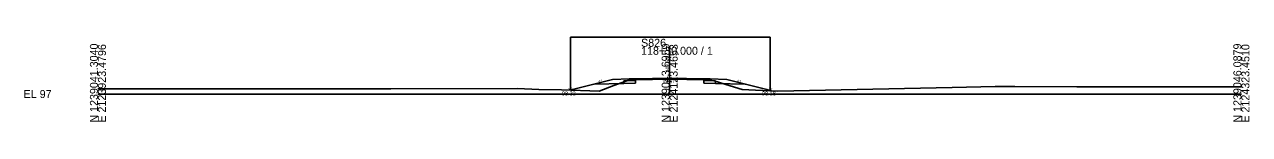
# Model space of a CAD drawing. Extents: x 2119282 to 2119710, y 1215030 to 1220057.
# Drawn here: x 2119281.9 to 2119710.4, y 1217030.1 to 1217059.7 of the extents above; entities that cross this region are included whole.
import ezdxf

# ---------------------------------------------------------------- set-up
doc = ezdxf.new("R2010")
doc.units = 0
for name, color, linetype in [('XS_CELL', 7, 'Continuous'), ('XS_M_DITCH', 7, 'Continuous'), ('XS_P_FINISHED_GRADE', 7, 'Continuous'), ('XS_P_FINISHED_GRADE_ELEV_TX', 7, 'Continuous'), ('XS_P_SUBGRADE_GRANULAR', 7, 'Continuous'), ('XS_P_SUBGRADE_PAVEMENT', 7, 'Continuous'), ('XS_P_TX_DCH', 7, 'Continuous'), ('XS_P_TX_FS_BS', 7, 'Continuous'), ('XS_X_GROUND', 7, 'Continuous'), ('XS_X_GROUND_TX', 7, 'Continuous')]:
    doc.layers.add(name, color=color, linetype=linetype)

msp = doc.modelspace()

# ---------------------------------------------------------------- linework, layer by layer
at = {"layer": 'XS_CELL'}
for p, q in [((2119507.6, 1217039.8), (2119507.6, 1217056.36)), ((2119307.6, 1217039.8), (2119507.6, 1217039.8)), ((2119507.6, 1217039.8), (2119707.6, 1217039.8))]:
    msp.add_line(p, q, dxfattribs=at)
at = {"layer": 'XS_M_DITCH'}
for p, q in [((2119472.87, 1217041.13), (2119472.87, 1217059.68)), ((2119472.87, 1217059.68), (2119542.77, 1217059.68)), ((2119542.77, 1217040.98), (2119542.77, 1217059.68))]:
    msp.add_line(p, q, dxfattribs=at)
at = {"layer": 'XS_P_FINISHED_GRADE'}
for p, q in [((2119473.6, 1217041.37), (2119472.87, 1217041.13)), ((2119487.6, 1217044.87), (2119473.6, 1217041.37)), ((2119493.6, 1217045.11), (2119487.6, 1217044.87)), ((2119495.6, 1217045.15), (2119493.6, 1217045.11)), ((2119507.6, 1217045.39), (2119495.6, 1217045.15)), ((2119507.6, 1217045.39), (2119519.6, 1217045.15)), ((2119519.6, 1217045.15), (2119521.6, 1217045.11)), ((2119521.6, 1217045.11), (2119527.6, 1217044.87)), ((2119527.6, 1217044.87), (2119541.6, 1217041.37)), ((2119541.6, 1217041.37), (2119542.77, 1217040.98))]:
    msp.add_line(p, q, dxfattribs=at)
at = {"layer": 'XS_P_SUBGRADE_GRANULAR'}
for p, q in [((2119491.6, 1217043.49), (2119481.24, 1217043.28)), ((2119492.95, 1217044.52), (2119491.6, 1217044.46)), ((2119491.6, 1217043.49), (2119491.6, 1217044.46)), ((2119495.6, 1217043.57), (2119491.6, 1217043.49)), ((2119495.6, 1217043.57), (2119495.61, 1217044.57)), ((2119519.6, 1217043.57), (2119519.59, 1217044.57)), ((2119519.6, 1217043.57), (2119523.6, 1217043.49)), ((2119522.26, 1217044.52), (2119523.6, 1217044.46)), ((2119523.6, 1217043.49), (2119523.6, 1217044.46)), ((2119523.6, 1217043.49), (2119533.97, 1217043.28))]:
    msp.add_line(p, q, dxfattribs=at)
at = {"layer": 'XS_P_SUBGRADE_PAVEMENT'}
for p, q in [((2119493.1, 1217044.77), (2119492.95, 1217044.52)), ((2119495.61, 1217044.57), (2119492.95, 1217044.52)), ((2119493.6, 1217045.11), (2119493.1, 1217044.77)), ((2119507.6, 1217045.06), (2119495.61, 1217044.82)), ((2119495.61, 1217044.57), (2119495.61, 1217044.82)), ((2119507.6, 1217045.06), (2119519.6, 1217044.82)), ((2119519.59, 1217044.57), (2119519.6, 1217044.82)), ((2119519.59, 1217044.57), (2119522.26, 1217044.52)), ((2119521.6, 1217045.11), (2119522.11, 1217044.77)), ((2119522.11, 1217044.77), (2119522.26, 1217044.52))]:
    msp.add_line(p, q, dxfattribs=at)
at = {"layer": 'XS_X_GROUND'}
for p, q in [((2119307.6, 1217041.57), (2119317.98, 1217041.6)), ((2119317.98, 1217041.6), (2119364.19, 1217041.64)), ((2119364.19, 1217041.64), (2119410.07, 1217041.64)), ((2119410.07, 1217041.64), (2119454.34, 1217041.72)), ((2119454.34, 1217041.72), (2119461.78, 1217041.44)), ((2119461.78, 1217041.44), (2119469.79, 1217041.24)), ((2119469.79, 1217041.24), (2119482.91, 1217040.76)), ((2119482.91, 1217040.76), (2119488.07, 1217042.78)), ((2119488.07, 1217042.78), (2119493.96, 1217044.9)), ((2119493.96, 1217044.9), (2119496.66, 1217045.12)), ((2119496.66, 1217045.12), (2119498.93, 1217045.16)), ((2119498.93, 1217045.16), (2119507.6, 1217045.31)), ((2119507.6, 1217045.31), (2119508.36, 1217045.32)), ((2119508.36, 1217045.32), (2119520.27, 1217044.72)), ((2119520.27, 1217044.72), (2119523.16, 1217044.44)), ((2119523.16, 1217044.44), (2119528.81, 1217042.63)), ((2119528.81, 1217042.63), (2119532.91, 1217041.39)), ((2119532.91, 1217041.39), (2119537.58, 1217041.21)), ((2119537.58, 1217041.21), (2119545.48, 1217040.86)), ((2119545.48, 1217040.86), (2119606.45, 1217042.09)), ((2119606.45, 1217042.09), (2119621.43, 1217042.39)), ((2119621.43, 1217042.39), (2119628.3, 1217042.4)), ((2119628.3, 1217042.4), (2119650.07, 1217042.38)), ((2119650.07, 1217042.38), (2119707.6, 1217042.38))]:
    msp.add_line(p, q, dxfattribs=at)

# ---------------------------------------------------------------- texts
at = {"layer": 'XS_CELL'}
for s, p in [('S826', (2119497.6, 1217056.36)), ('118+50.000 / 1', (2119497.6, 1217053.56)), ('EL 97', (2119281.6, 1217038.4))]:
    msp.add_text(s, height=2.8, dxfattribs=at).set_placement(p)
for s, p in [('N 1239041.3040', (2119307.6, 1217029.8)), ('E 2123923.4796', (2119310.4, 1217029.8)), ('N 1239043.6959', (2119507.6, 1217029.8)), ('E 2124123.4653', (2119510.4, 1217029.8)), ('N 1239046.0879', (2119707.6, 1217029.8)), ('E 2124323.4510', (2119710.4, 1217029.8))]:
    msp.add_text(s, height=2.8, rotation=90, dxfattribs=at).set_placement(p)
at = {"layer": 'XS_P_FINISHED_GRADE_ELEV_TX'}
msp.add_text('102.59', height=1.25, rotation=90, dxfattribs=at).set_placement((2119507.45, 1217047.47))
at = {"layer": 'XS_P_TX_DCH'}
for s, p in [('98.32', (2119469.89, 1217039.3)), ('98.18', (2119539.87, 1217039.3))]:
    msp.add_text(s, height=1.4, dxfattribs=at).set_placement(p)
at = {"layer": 'XS_P_TX_FS_BS'}
for s, rotation, p in [('3:1', 18.4349, (2119472.34, 1217041.02)), ('4:1', 14.0362, (2119482.77, 1217043.84)), ('4:1', 345.9638, (2119531.11, 1217044.17)), ('3:1', 341.5651, (2119542.02, 1217041.45))]:
    msp.add_text(s, height=0.8, rotation=rotation, dxfattribs=at).set_placement(p)
at = {"layer": 'XS_X_GROUND_TX'}
msp.add_text('102.51', height=1, dxfattribs=at).set_placement((2119505.03, 1217043.61))

doc.saveas('drawing.dxf')
